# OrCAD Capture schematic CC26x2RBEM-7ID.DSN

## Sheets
1 Mechanical: size A4; title: CC26x2RBEM-7ID; rev: B0
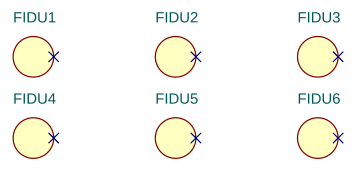
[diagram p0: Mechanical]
2 Revision
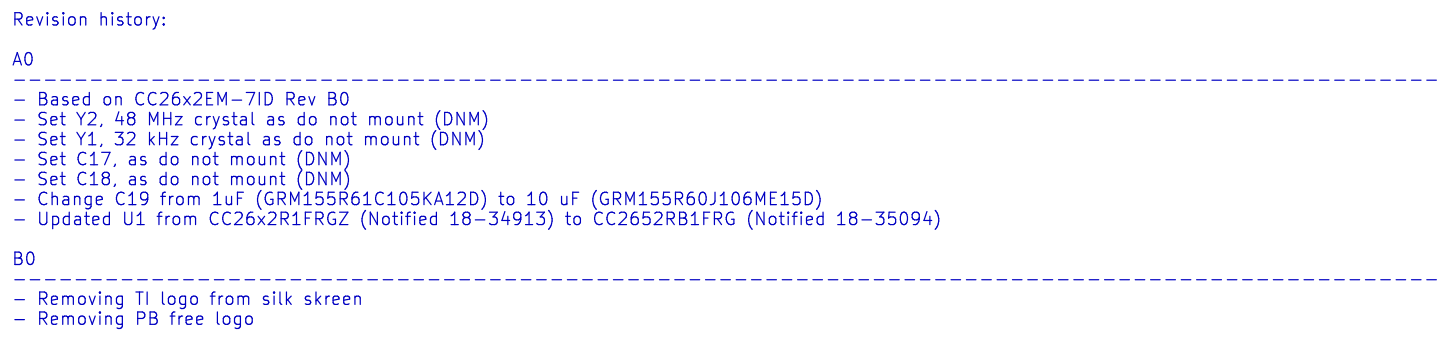
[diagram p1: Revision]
3 CC26x2RBEM-7ID: size A3
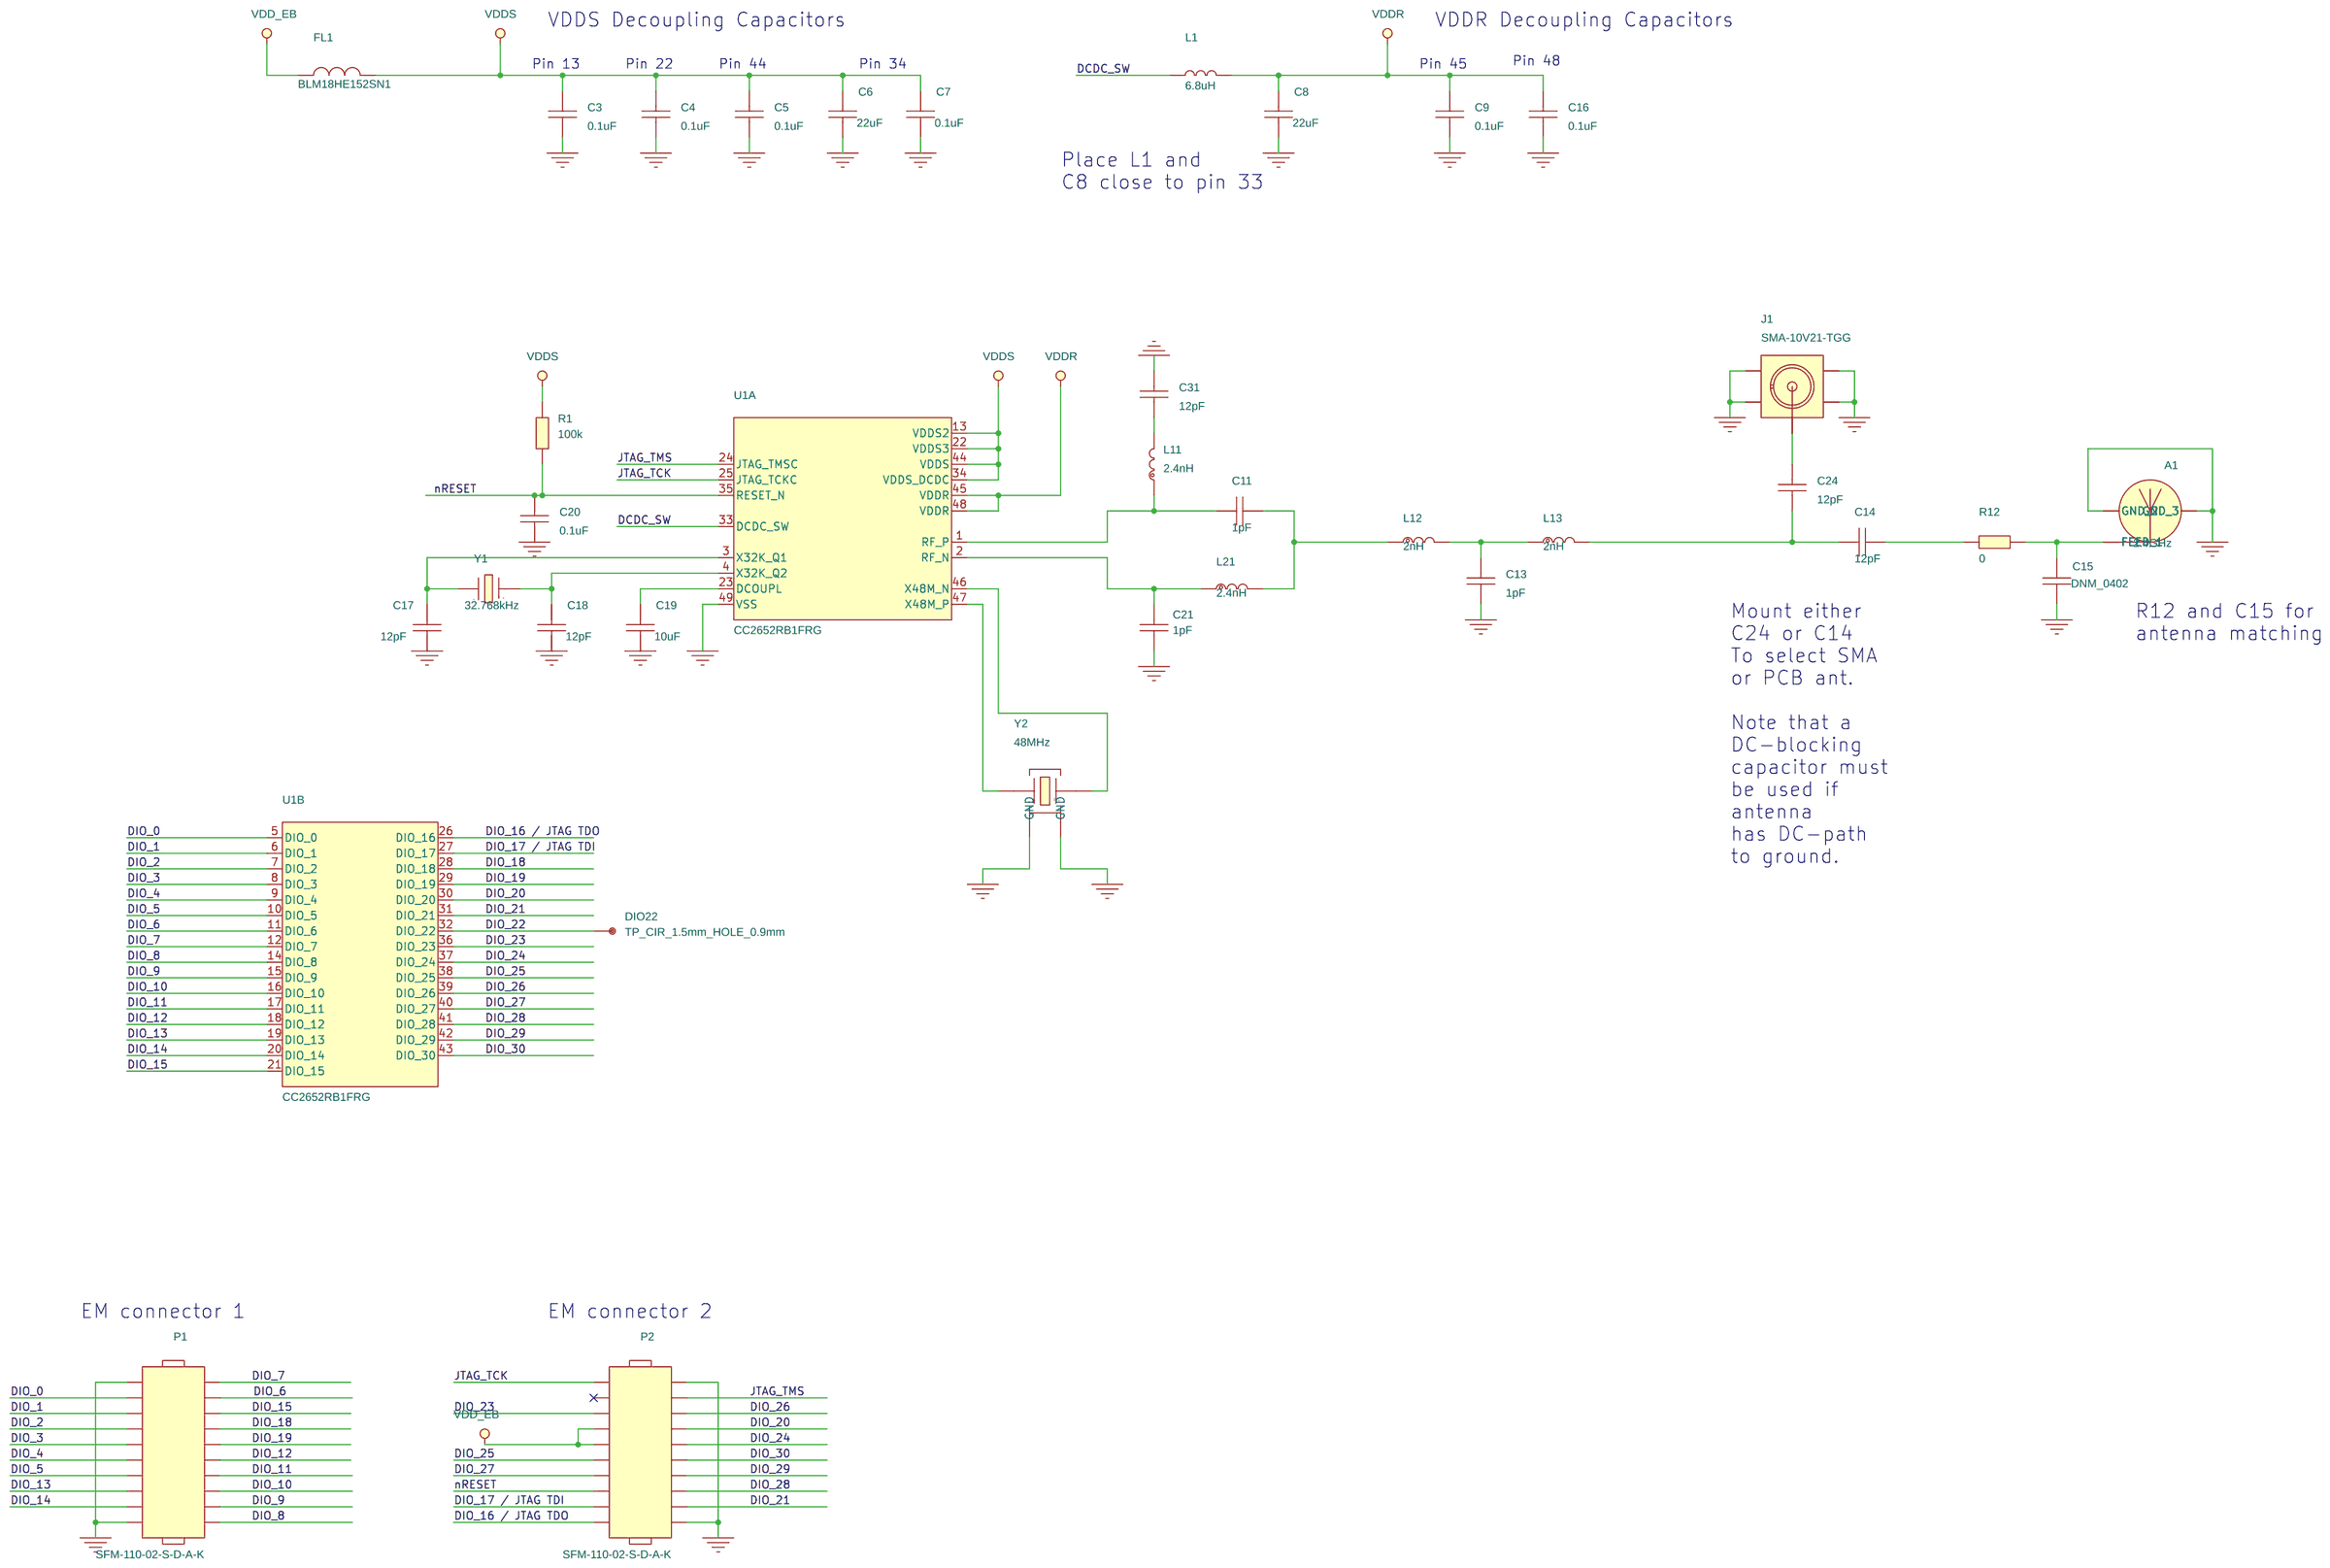
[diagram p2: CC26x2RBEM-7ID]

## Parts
sheet CC26x2RBEM-7ID
A1  2.4GHz  [ANTENNA_DN007AN]
C3  0.1uF  [CAPC1005X60B2N]
C4  0.1uF  [CAPC1005X60B2N]
C5  0.1uF  [CAPC1005X60B2N]
C6  22uF  [CAPC1608X100A2N]
C7  0.1uF  [CAPC1005X60B2N]
C8  22uF  [CAPC1608X100A2N]
C9  0.1uF  [CAPC1005X60B2N]
C11  1pF  [CAPC1005X60B2N]
C13  1pF  [CAPC1005X60B2N]
C14  12pF  [CAPC1005X60B2N]
C15  DNM_0402  [CAPC1005X60B2N]
C16  0.1uF  [CAPC1005X60B2N]
C17  12pF  [CAPC1005X60B2N]
C18  12pF  [CAPC1005X60B2N]
C19  10uF  [CAPC1005X65B2N]
C20  0.1uF  [CAPC1005X60B2N]
C21  1pF  [CAPC1005X60B2N]
C24  12pF  [CAPC1005X60B2N]
C31  12pF  [CAPC1005X60B2N]
DIO22  TP_CIR_1.5mm_HOLE_0.9mm  [TP150_90H]
FL1  BLM18HE152SN1  [FIL_BLM18HE152SN1DN]
J1  SMA-10V21-TGG  [HUSTSAN_SMA10V21TGGAN]
L1  6.8uH  [INDC2012X150A2N]
L11  2.4nH  [INDC1005X60D2N]
L12  2nH  [INDC1005X60D2N]
L13  2nH  [INDC1005X60D2N]
L21  2.4nH  [INDC1005X60D2N]
P1  SFM-110-02-S-D-A-K  [SAMTEC_SFM11002AN]
P2  SFM-110-02-S-D-A-K  [SAMTEC_SFM11002AN]
R1  100k  [RESC1005X40B2N]
R12  0  [RESC1005X40B2N]
U1  CC2652RB1FRG  [QFNFC50P700X700X100-49A2N]  (sections A,B)
Y1  32.768kHz  [XTAL_FC135_A2N]
Y2  48MHz  [OSCCC200X160X50-4B2N]
sheet Mechanical
FIDU1  FIDU_1MM  [FID100X115B]
FIDU2  FIDU_1MM  [FID100X115B]
FIDU3  FIDU_1MM  [FID100X115B]
FIDU4  FIDU_1MM  [FID100X115B]
FIDU5  FIDU_1MM  [FID100X115B]
FIDU6  FIDU_1MM  [FID100X115B]

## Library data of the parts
A1 = ANTENNA_DN007: ANTENNA, NON COMPONENT, 2.4GHz INVERTED F ANTENNA, NOT APPLY; Additional Datasheet URL: N/A; AutoDoc File: https://notefied-dynamic-precision.com/DB/Apps/Desktop/Item/Object.aspx?id=85542; BU Name: DYNAMIC PRECISION GDANSK; Budget Currency: N/A; Budget Price: N/A; CLASS: DISCRETE; Client Status: UNDER_REVIEW; Country of Origin: Missing Info; Datasheet URL: www.ti.com; Datasheet URL 1: http://www.ti.com/lit/an/swru120b/swru120b.pdf; Datasheet URL 2: N/A; Definied Quality: INDUSTRIAL; Esd Level: HBM 500V; Exclusive for Customers: TEXAS INSTRUMENTS NORWAY; FPLIST: ANTENNA_DN007N,ANTENNA_DN007AN,; MPN: DN007; MPN Status: ACTIVE; MSL: N/A; MTBF: N/A; MTBF Standard: N/A; Manufacturer: TEXAS INSTRUMENTS; Mass: N/A; Max Oper Temp: +85DEGC; Maximum Operating Temperature: +85DEGC; Min Oper Temp: -40DEGC; Minimum Operating Temperature: -40DEGC; Mounting Type: Not Apply; NOTE Status: PREFERRED; NOTEfied URL: https://notefied-dynamic-precision.com/NOTEfiedWebInterface/part/show?partNumber=13-00347; Notes: Custom Item; Old Footprint: ANTENNA_DN007N,ANTENNA_DN007AN; Packing Size: N/A; Packing Type: Missing Info; Part Number: 13-00347; Part Type: Mechanic|ANTENNA|NON COMPONENT; ROHS: Not Applicable; Revision: R019; RoHS Status: NOT_APPLICABLE; Status: Released; Texas Part Status: Under Review; Type: Mechanic; Vendor: TEXAS INSTRUMENTS; Vendor Part Number: DN007; Vendor Part Status: Active; WEIGHT: N/A
C3-C5 C9 C16 C20 = CAPACITOR: CAPACITOR, CERAMIC X7R, 0.1uF, 25V, -10%/+10%, -55DEGC/+125DEGC, 0402, SMD; Additional Datasheet URL: https://search.murata.co.jp/Ceramy/image/img/A01X/G101/ENG/GRM155R71E104KE14-01A.pdf; AutoDoc File: https://notefied-dynamic-precision.com/DB/Apps/Desktop/Item/Object.aspx?id=115293; BU Name: TEXAS INSTRUMENTS NORWAY; Client Status: UNDER_REVIEW; Datasheet URL: https://www.murata.com/~/media/webrenewal/support/library/catalog/products/capacitor/mlcc/c02e.ashx?la=en-gb; Datasheet URL 1: http://psearch.murata.com/capacitor/product/GRM155R71E104KE14%23.pdf; Datasheet URL 2: N/A; Dielectric Type: X7R; LifeCycle Status: ACTIVE; MPN: GRM155R70J104KA01D; MPN Status: ACTIVE; Manufacturer: MURATA; Mass: 0.0016g; Max Oper Temp: +125DEGC; Max Tol: +10%; Maximum Operating Temperature: +125DEGC; Maximum Tolerance: +10%; Min Oper Temp: -55DEGC; Min Tol: -10%; Minimum Operating Temperature: -55DEGC; Minimum Tolerance: -10%; Mounting Type: SMD; NOTE Status: PREFERRED; NOTEfied URL: https://notefied-dynamic-precision.com/NOTEfiedWebInterface/part/show?partNumber=02-07861; Old Footprint: CAPC1005X60N,0402; PCB Package: 0402; Packing Size: 10000; Packing Type: Tape & Reel; Part Number: 02-07861; Part Type: Capacitor|CERAMIC|0402|STANDARD; REACH/SVHC Compliance: Compliant; REACH/SVHC Details: SVHC List Version Jul 7, 2017; REACH/SVHC Source: REACH Declaration; REACH/SVHC Status: Unaffected; REACH/SVHC_COMPLIANCE: COMPLIANT; REACH/SVHC_DETAILS: SVHC LIST VERSION Jun 20, 2016; REACH/SVHC_SOURCE: REACH DECLARATION; REACH/SVHC_STATUS: UNAFFECTED; ROHS: Compliant; Rated Voltage: 25V; Revision: R014; RoHS Status: ROHS_COMPLIANT; Rtd Voltage: 25V; Status: Released; Texas Part Status: Under Review; Type: Capacitor; Vendor: MURATA; Vendor Part Number: GRM155R71E104KE14D; Vendor Part Status: NRND; WEIGHT: 0.0016g
C6 C8 = CAPACITOR: CAPACITOR, CERAMIC, X5R, 22uF, 6.3V, -20%/+20%, -55DEGC/+85DEGC, 0603, SMD; ALT_SYMBOLS: CAPC1608X100A2L,CAPC1608X100A2M; Additional Datasheet URL: https://search.murata.co.jp/Ceramy/image/img/A01X/G101/ENG/GRM188R60J226MEA0-01A.pdf; AutoDoc File: https://notefied-dynamic-precision.com/DB/Apps/Desktop/Item/Object.aspx?id=104385; BU Name: DYNAMIC PRECISION GDANSK; Budget Currency: EUR; Budget Price: 0.062; Budgetary Price: 0.062 EUR; Client Status: UNDER_REVIEW; Country of Origin: Japan; Datasheet URL: https://www.murata.com/~/media/webrenewal/support/library/catalog/products/capacitor/mlcc/c02e.ashx?la=en-gb; Datasheet URL 1: http://psearch.murata.com/capacitor/product/GRM188R60J226MEA0%23.pdf; Datasheet URL 2: N/A; Definied Quality: INDUSTRIAL; Dielectric Type: X5R; Esd Level: N/A; Lead Time: 26; MPN: GRM188R60J106ME47D; MPN Status: NRND; MSL: 1; MTBF: N/A; MTBF Standard: N/A; Manufacturer: MURATA; Mass: 0.0091g; Max Oper Temp: +85DEGC; Max Tol: +20%; Maximum Operating Temperature: +85DEGC; Maximum Tolerance: +20%; Min Oper Temp: -55DEGC; Min Tol: -20%; Minimum Operating Temperature: -55DEGC; Minimum Tolerance: -20%; Mounting Type: SMD; NOTE Status: PREFERRED; NOTEfied URL: https://notefied-dynamic-precision.com/NOTEfiedWebInterface/part/show?partNumber=02-07053; Old Footprint: CAPC1608X90N; PCB Package: 0603; Packing Size: 4000; Packing Type: Tape & Reel; Part Number: 02-07053; Part Type: Capacitor|CERAMIC|0603|STANDARD; REACH/SVHC Compliance: Compliant; REACH/SVHC Details: SVHC List Version Jul 7, 2017; REACH/SVHC Source: REACH Declaration; REACH/SVHC Status: Unaffected; REACH/SVHC_COMPLIANCE: COMPLIANT; REACH/SVHC_DETAILS: SVHC LIST VERSION Dec 17, 2015; REACH/SVHC_SOURCE: REACH DECLARATION; REACH/SVHC_STATUS: UNAFFECTED; ROHS: Compliant; Rated Voltage: 6.3V; Revision: R016; RoHS Status: ROHS_COMPLIANT; Rtd Voltage: 6.3V; Status: Released; Texas Part Status: Under Review; Type: Capacitor; Vendor: MURATA; Vendor Part Number: GRM188R60J226MEA0D; Vendor Part Status: Active; WEIGHT: 0.0091g
C7 = CAPACITOR: CAPACITOR, CERAMIC X7R, 0.1uF, 25V, -10%/+10%, -55DEGC/+125DEGC, 0402, SMD; Additional Datasheet URL: https://search.murata.co.jp/Ceramy/image/img/A01X/G101/ENG/GRM155R71E104KE14-01A.pdf; AutoDoc File: https://notefied-dynamic-precision.com/DB/Apps/Desktop/Item/Object.aspx?id=115293; BU Name: TEXAS INSTRUMENTS NORWAY; Cage Code: C0151; Client Status: UNDER_REVIEW; Datasheet URL: https://www.murata.com/~/media/webrenewal/support/library/catalog/products/capacitor/mlcc/c02e.ashx?la=en-gb; Datasheet URL 1: http://psearch.murata.com/capacitor/product/GRM155R71E104KE14%23.pdf; Datasheet URL 2: N/A; Dielectric Type: X7R; MPN: GRM188R71E104KA01D; MPN Status: ACTIVE; Manufacturer: MURATA; Mass: 0.0016g; Max Oper Temp: +125DEGC; Max Tol: +10%; Maximum Operating Temperature: +125DEGC; Maximum Tolerance: +10%; Min Oper Temp: -55DEGC; Min Tol: -10%; Minimum Operating Temperature: -55DEGC; Minimum Tolerance: -10%; Mounting Type: SMD; NOTE Status: PREFERRED; NOTEfied URL: https://notefied-dynamic-precision.com/NOTEfiedWebInterface/part/show?partNumber=02-07861; Old Footprint: CAPC1608X90N,0603; PCB Package: 0402; Packing Size: 10000; Packing Type: Tape & Reel; Part Number: 02-07861; Part Type: Capacitor|CERAMIC|0402|STANDARD; REACH/SVHC Compliance: Compliant; REACH/SVHC Details: SVHC List Version Jul 7, 2017; REACH/SVHC Source: REACH Declaration; REACH/SVHC Status: Unaffected; REACH/SVHC_COMPLIANCE: COMPLIANT; REACH/SVHC_DETAILS: SVHC LIST VERSION Jun 20, 2016; REACH/SVHC_SOURCE: REACH DECLARATION; REACH/SVHC_STATUS: UNAFFECTED; ROHS: Compliant; Rated Voltage: 25V; Revision: R014; RoHS Status: ROHS_COMPLIANT; Rtd Voltage: 25V; Status: Released; Texas Part Status: Under Review; Type: Capacitor; Vendor: MURATA; Vendor Part Number: GRM155R71E104KE14D; Vendor Part Status: NRND; WEIGHT: 0.0016g
C11 C13 C21 = CAPACITOR: CAPACITOR, CERAMIC C0G/NP0, 1pF, 50V, -0.25pF/ +0.25pF, -55DEGC/+125DEGC, 0402, SMD; Additional Datasheet URL: https://search.murata.co.jp/Ceramy/image/img/A01X/G101/ENG/GRM1555C1H1R0CA01-01A.pdf; AutoDoc File: https://notefied-dynamic-precision.com/DB/Apps/Desktop/Item/Object.aspx?id=113355; BU Name: TEXAS INSTRUMENTS NORWAY; Budget Currency: EUR; Budget Price: 0.006; Budgetary Price: 0.006 EUR; Country of Origin: Philippines; Datasheet URL: https://www.murata.com/~/media/webrenewal/support/library/catalog/products/capacitor/mlcc/c02e.ashx?la=en-gb; Datasheet URL 1: http://psearch.murata.com/capacitor/product/GRM1555C1H1R0CA01%23.pdf; Datasheet URL 2: http://search.murata.co.jp/Ceramy/image/img/w_hinm/L0005E.pdf; Dielectric Type: C0G/NP0; Exclusive for Customers: TEXAS INSTRUMENTS NORWAY; Lead Time: 12; MPN: GRM1555C1H1R0CA01D; MPN Status: ACTIVE; Manufacturer: MURATA; Mass: 0.0016g; Max Oper Temp: +125DEGC; Max Tol: +0.25pF; Maximum Operating Temperature: +125DEGC; Maximum Tolerance: +0.25pF; Min Oper Temp: -55DEGC; Min Tol: -0.25pF; Minimum Operating Temperature: -55DEGC; Minimum Tolerance: -0.25pF; Mounting Type: SMD; NOTE Status: PREFERRED; NOTEfied URL: https://notefied-dynamic-precision.com/NOTEfiedWebInterface/part/show?partNumber=02-07627; Notes: Standard item: Duplicate Reason: custom footprint for TEXAS INSTRUMENTS NORWAY.; Old Footprint: CAPC1005X60N; PCB Package: 0402; Packing Size: 10000; Packing Type: Tape & Reel; Part Number: 02-07627; Part Type: Capacitor|CERAMIC|0402|STANDARD; REACH/SVHC Compliance: Compliant; REACH/SVHC Details: SVHC List Version Jul 7, 2017; REACH/SVHC Source: REACH Declaration; REACH/SVHC Status: Unaffected; REACH/SVHC_COMPLIANCE: COMPLIANT; REACH/SVHC_DETAILS: SVHC LIST VERSION Dec 17, 2015; REACH/SVHC_SOURCE: REACH DECLARATION; REACH/SVHC_STATUS: UNAFFECTED; ROHS: Compliant; Rated Voltage: 50V; Revision: R016; RoHS Status: ROHS_COMPLIANT; Rtd Voltage: 50V; Status: Released; Texas Part Status: Under Review; Type: Capacitor; Vendor: MURATA; Vendor Part Number: GRM1555C1H1R0CA01D; Vendor Part Status: NRND; WEIGHT: 0.0016g
C14 C24 = CAPACITOR: CAPACITOR, CERAMIC C0G/NP0, 12pF, 50V, -5%/+5%, -55DEGC/+125DEGC, 0402, SMD; Additional Datasheet URL: https://search.murata.co.jp/Ceramy/image/img/A01X/G101/ENG/GRM1555C1H120JA01-01A.pdf; AutoDoc File: https://notefied-dynamic-precision.com/DB/Apps/Desktop/Item/Object.aspx?id=113345; BU Name: TEXAS INSTRUMENTS NORWAY; Budget Currency: EUR; Budget Price: 0.007; Budgetary Price: 0.007 EUR; Country of Origin: Philippines; Datasheet URL: https://www.murata.com/~/media/webrenewal/support/library/catalog/products/capacitor/mlcc/c02e.ashx?la=en-gb; Datasheet URL 1: http://psearch.murata.com/capacitor/product/GRM1555C1H120JA01%23.pdf; Datasheet URL 2: http://search.murata.co.jp/Ceramy/image/img/w_hinm/L0005E.pdf; Dielectric Type: C0G/NP0; Exclusive for Customers: TEXAS INSTRUMENTS NORWAY; Lead Time: 12; MPN: GRM1555C1H120JA01D; MPN Status: ACTIVE; Manufacturer: MURATA; Mass: 0.0016g; Max Oper Temp: +125DEGC; Max Tol: +5%; Maximum Operating Temperature: +125DEGC; Maximum Tolerance: +5%; Min Oper Temp: -55DEGC; Min Tol: -5%; Minimum Operating Temperature: -55DEGC; Minimum Tolerance: -5%; Mounting Type: SMD; NOTE Status: PREFERRED; NOTEfied URL: https://notefied-dynamic-precision.com/NOTEfiedWebInterface/part/show?partNumber=02-07617; Notes: Standard item: Duplicate Reason: custom footprint for TEXAS INSTRUMENTS NORWAY.; Old Footprint: CAPC1005X60N; PCB Package: 0402; Packing Size: 10000; Packing Type: Tape & Reel; Part Number: 02-07617; Part Type: Capacitor|CERAMIC|0402|STANDARD; REACH/SVHC Compliance: Compliant; REACH/SVHC Details: SVHC List Version Jul 7, 2017; REACH/SVHC Source: REACH Declaration; REACH/SVHC Status: Unaffected; REACH/SVHC_COMPLIANCE: COMPLIANT; REACH/SVHC_DETAILS: SVHC LIST VERSION Dec 17, 2015; REACH/SVHC_SOURCE: REACH DECLARATION; REACH/SVHC_STATUS: UNAFFECTED; ROHS: Compliant; Rated Voltage: 50V; Revision: R016; RoHS Status: ROHS_COMPLIANT; Rtd Voltage: 50V; Status: Released; Texas Part Status: Under Review; Type: Capacitor; Vendor: MURATA; Vendor Part Number: GRM1555C1H120JA01D; Vendor Part Status: NRND; WEIGHT: 0.0016g
C15 = CAPACITOR: CAPACITOR, CERAMIC, TBD, 0402, SMD, DNM; Additional Datasheet URL: N/A; AutoDoc File: https://notefied-dynamic-precision.com/DB/Apps/Desktop/Item/Object.aspx?id=113344; BU Name: TEXAS INSTRUMENTS NORWAY; Country of Origin: Missing Info; Datasheet URL: N/A; Datasheet URL 1: N/A; Datasheet URL 2: N/A; Dielectric Type: MISSING-INFO; Exclusive for Customers: TEXAS INSTRUMENTS NORWAY; MPN: CAPACITOR_0402_DNM_N/A_M; MPN Status: ACTIVE; Manufacturer: Manufacturer selection; Mass: N/A; Max Oper Temp: +125DEGC; Maximum Operating Temperature: +125DEGC; Min Oper Temp: -55DEGC; Minimum Operating Temperature: -55DEGC; Mounting Type: SMD; NOTE Status: PREFERRED; NOTEfied URL: https://notefied-dynamic-precision.com/NOTEfiedWebInterface/part/show?partNumber=02-07616; Notes: Standard item: Duplicate Reason: custom footprint for TEXAS INSTRUMENTS NORWAY.; Old Footprint: CAPC1005X60N; PCB Package: 0402; Part Number: 02-07616; Part Type: Capacitor|CERAMIC|0402|STANDARD; ROHS: Compliant; Revision: R014; RoHS Status: ROHS_COMPLIANT; Status: Released; Texas Part Status: Under Review; Type: Capacitor; Vendor: MANUFACTURER SELECTION; Vendor Part Number: CAPACITOR_TBD_0402_DNM; Vendor Part Status: Active; Weight: N/A
C17 C18 = CAPACITOR: CAPACITOR, CERAMIC C0G/NP0, 12pF, 50V, -5%/+5%, -55DEGC/+125DEGC, 0402, SMD; Additional Datasheet URL: https://search.murata.co.jp/Ceramy/image/img/A01X/G101/ENG/GRM1555C1H120JA01-01A.pdf; AutoDoc File: https://notefied-dynamic-precision.com/DB/Apps/Desktop/Item/Object.aspx?id=113345; BU Name: TEXAS INSTRUMENTS NORWAY; Budget Currency: EUR; Budget Price: 0.007; Budgetary Price: 0.007 EUR; Country of Origin: Philippines; Datasheet URL: https://www.murata.com/~/media/webrenewal/support/library/catalog/products/capacitor/mlcc/c02e.ashx?la=en-gb; Datasheet URL 1: http://psearch.murata.com/capacitor/product/GRM1555C1H120JA01%23.pdf; Datasheet URL 2: http://search.murata.co.jp/Ceramy/image/img/w_hinm/L0005E.pdf; Definied Quality: INDUSTRIAL; Dielectric Type: C0G/NP0; Esd Level: N/A; Exclusive for Customers: TEXAS INSTRUMENTS NORWAY; Lead Time: 12; LifeCycle Status: ACTIVE; MPN: CAPACITOR_0402_12pF_C0G/NP0_M_+/-5%_50V; MPN Status: ACTIVE; MSL: N/A; MTBF: N/A; MTBF Standard: N/A; Manufacturer: MANUFACTURER SELECTION; Mass: 0.0016g; Max Oper Temp: +125DEGC; Max Tol: +5%; Maximum Operating Temperature: +125DEGC; Maximum Tolerance: +5%; Min Oper Temp: -55DEGC; Min Tol: -5%; Minimum Operating Temperature: -55DEGC; Minimum Tolerance: -5%; Mounting Type: SMD; NOTE Status: PREFERRED; NOTEfied URL: https://notefied-dynamic-precision.com/NOTEfiedWebInterface/part/show?partNumber=02-07617; Notes: Standard item: Duplicate Reason: custom footprint for TEXAS INSTRUMENTS NORWAY.; Old Footprint: CAPC1005X60N; PCB Package: 0402; Packing Size: 10000; Packing Type: Tape & Reel; Part Number: 02-07617; Part Type: Capacitor|CERAMIC|0402|STANDARD; REACH/SVHC Compliance: Compliant; REACH/SVHC Details: SVHC List Version Jul 7, 2017; REACH/SVHC Source: REACH Declaration; REACH/SVHC Status: Unaffected; REACH/SVHC_COMPLIANCE: COMPLIANT; REACH/SVHC_DETAILS: SVHC LIST VERSION Dec 17, 2015; REACH/SVHC_SOURCE: REACH DECLARATION; REACH/SVHC_STATUS: UNAFFECTED; ROHS: Compliant; Rated Voltage: 50V; Revision: R016; RoHS Status: ROHS_COMPLIANT; Rtd Voltage: 50V; Status: Released; Texas Part Status: Under Review; Type: Capacitor; Vendor: MURATA; Vendor Part Number: GRM1555C1H120JA01D; Vendor Part Status: NRND; WEIGHT: 0.0016g
C19 = CAPACITOR: CAPACITOR, CERAMIC X5R, 10uF, 6.3V, -20%/+20%, -55DEGC/+85DEGC, 0402, SMD; Additional Datasheet URL: https://psearch.en.murata.com/capacitor/product/GRM155R60J106ME15%23.pdf?graph=1052f0115a5050a7826442b7332e4634; AutoDoc File: https://notefied-dynamic-precision.com/DB/Apps/Desktop/Item/Object.aspx?id=115295; BU Name: TEXAS INSTRUMENTS NORWAY; Client Status: UNDER_REVIEW; Datasheet URL: https://search.murata.co.jp/Ceramy/image/img/A01X/G101/ENG/GRM155R60J106ME15-01A.pdf; Datasheet URL 1: http://psearch.murata.com/capacitor/product/GRM155R61C105KA12%23.pdf; Datasheet URL 2: N/A; Definied Quality: INDUSTRIAL; Dielectric Type: X5R; Esd Level: N/A; MPN: GRM155R61A105KE15D; MPN Status: ACTIVE; MSL: 1; MTBF: N/A; MTBF Standard: N/A; Manufacturer: MURATA; Mass: 0.0025g; Max Oper Temp: +85DEGC; Max Tol: +10%; Maximum Operating Temperature: +85DEGC; Maximum Tolerance: +20%; Min Oper Temp: -55DEGC; Min Tol: -10%; Minimum Operating Temperature: -55DEGC; Minimum Tolerance: -20%; Mounting Type: SMD; NOTE Status: PREFERRED; NOTEfied URL: https://notefied-dynamic-precision.com/NOTEfiedWebInterface/part/show?partNumber=02-09408; Old Footprint: CAPC1005X60N,0402; PCB Package: 0402; Packing Size: 10000; Packing Type: Tape & Reel; Part Number: 02-09408; Part Type: Capacitor|CERAMIC|0402|STANDARD; REACH/SVHC Compliance: Compliant; REACH/SVHC Details: SVHC List Version Jul 16, 2019; REACH/SVHC Source: REACH Declaration; REACH/SVHC Status: Unaffected; REACH/SVHC_COMPLIANCE: COMPLIANT; REACH/SVHC_DETAILS: SVHC LIST VERSION Jun 20, 2016; REACH/SVHC_SOURCE: REACH DECLARATION; REACH/SVHC_STATUS: UNAFFECTED; ROHS: Compliant; Rated Voltage: 6.3V; Revision: R001; RoHS Status: ROHS_COMPLIANT; Rtd Voltage: 16V; Status: Released; Texas Part Status: Under Review; Type: Capacitor; Vendor: MURATA; Vendor Part Number: GRM155R60J106ME15D; Vendor Part Status: Active; WEIGHT: 0.0016g
C31 = CAPACITOR: CAPACITOR, CERAMIC C0G/NP0, 12pF, 50V, -5%/+5%, -55DEGC/+125DEGC, 0402, SMD; Additional Datasheet URL: https://search.murata.co.jp/Ceramy/image/img/A01X/G101/ENG/GRM1555C1H120JA01-01A.pdf; AutoDoc File: https://notefied-dynamic-precision.com/DB/Apps/Desktop/Item/Object.aspx?id=113345; BU Name: TEXAS INSTRUMENTS NORWAY; Budget Currency: EUR; Budget Price: 0.007; Budgetary Price: 0.007 EUR; Country of Origin: Philippines; Datasheet URL: https://www.murata.com/~/media/webrenewal/support/library/catalog/products/capacitor/mlcc/c02e.ashx?la=en-gb; Datasheet URL 1: http://psearch.murata.com/capacitor/product/GRM1555C1H120JA01%23.pdf; Datasheet URL 2: http://search.murata.co.jp/Ceramy/image/img/w_hinm/L0005E.pdf; Dielectric Type: C0G/NP0; Exclusive for Customers: TEXAS INSTRUMENTS NORWAY; Lead Time: 12; MPN: GRM1555C1H6R8CA01D; MPN Status: ACTIVE; Manufacturer: MURATA; Mass: 0.0016g; Max Oper Temp: +125DEGC; Max Tol: +5%; Maximum Operating Temperature: +125DEGC; Maximum Tolerance: +5%; Min Oper Temp: -55DEGC; Min Tol: -5%; Minimum Operating Temperature: -55DEGC; Minimum Tolerance: -5%; Mounting Type: SMD; NOTE Status: PREFERRED; NOTEfied URL: https://notefied-dynamic-precision.com/NOTEfiedWebInterface/part/show?partNumber=02-07617; Notes: Standard item: Duplicate Reason: custom footprint for TEXAS INSTRUMENTS NORWAY.; Old Footprint: CAPC1005X60N; PCB Package: 0402; Packing Size: 10000; Packing Type: Tape & Reel; Part Number: 02-07617; Part Type: Capacitor|CERAMIC|0402|STANDARD; REACH/SVHC Compliance: Compliant; REACH/SVHC Details: SVHC List Version Jul 7, 2017; REACH/SVHC Source: REACH Declaration; REACH/SVHC Status: Unaffected; REACH/SVHC_COMPLIANCE: COMPLIANT; REACH/SVHC_DETAILS: SVHC LIST VERSION Dec 17, 2015; REACH/SVHC_SOURCE: REACH DECLARATION; REACH/SVHC_STATUS: UNAFFECTED; ROHS: Compliant; Rated Voltage: 50V; Revision: R016; RoHS Status: ROHS_COMPLIANT; Rtd Voltage: 50V; Status: Released; Texas Part Status: Under Review; Type: Capacitor; Vendor: MURATA; Vendor Part Number: GRM1555C1H120JA01D; Vendor Part Status: NRND; WEIGHT: 0.0016g
DIO22 = TEST_POINT: NON COMPONENT, TEST POINT, CIRCULAR 1.5mm, HOLE 0.9mm, PTH; Additional Datasheet URL: N/A; AutoDoc File: https://notefied-dynamic-precision.com/DB/Apps/Desktop/Item/Object.aspx?id=84966; BU Name: DYNAMIC PRECISION GDANSK; CLASS: IO; Country of Origin: Missing Info; Datasheet URL: N/A; FPLIST: TP150_90H,; Mass: N/A; Mounting Type: PTH; NOTEfied URL: https://notefied-dynamic-precision.com/NOTEfiedWebInterface/part/show?partNumber=19-00299; Packing Size: N/A; Packing Type: Missing Info; Part Number: 19-00299; Part Type: Non Component|TEST POINT; ROHS: Not Applicable; Revision: R018; Status: Released; Texas Part Status: Under Review; Type: Non Component; Vendor: NON_COMPONENT; Vendor Part Status: Active
FL1 = FILTER_2PIN: FILTER, EMI, FERRITE BEAD, 1500@100MHz, -25%/+25%, -55DEGC/+125DEGC, 0603, SMD; ALT_SYMBOLS: FIL_BLM18HE152SN1DL,FIL_BLM18HE152SN1DM; Additional Datasheet URL: https://www.murata.com/en-eu/products/productdata/8796741599262/ENFA0004.pdf?1441769419000; AutoDoc File: https://notefied-dynamic-precision.com/DB/Apps/Desktop/Item/Object.aspx?id=85575; BU Name: DYNAMIC PRECISION GDANSK; Budget Currency: EUR; Budget Price: 0.065; Budgetary Price: 0.065 EUR; CLASS: IC; Client Status: UNDER_REVIEW; Country of Origin: Japan,Singapore,Thailand; Datasheet URL: https://www.murata.com/~/media/webrenewal/support/library/catalog/products/emc/emifil/c31e.ashx; Datasheet URL 1: http://search.murata.co.jp/Ceramy/image/img/PDF/ENG/L0110S0101BLM18H.pdf; Datasheet URL 2: http://search.murata.co.jp/Ceramy/image/img/w_hinm/L0110E.pdf; Frequency: 100MHz; Impedance: 1500; Inductance: N/A; Lead Time: 9; MPN: BLM18HE152SN1D; MPN Status: ACTIVE; Manufacturer: MURATA; Mass: 0.006g; Max Oper Temp: +125DEGC; Max Tol: +25%; Maximum Operating Temperature: +125DEGC; Maximum Tolerance: +25%; Min Oper Temp: -55DEGC; Min Tol: -25%; Minimum Operating Temperature: -55DEGC; Minimum Tolerance: -25%; Mounting Type: SMD; NOTE Status: PREFERRED; NOTEfied URL: https://notefied-dynamic-precision.com/NOTEfiedWebInterface/part/show?partNumber=04-00470; PCB Package: 0603; Packing Size: 4000; Packing Type: Tape & Reel; Part Number: 04-00470; Part Type: Filter|EMI|FERRITE BEAD|0603; REACH/SVHC Compliance: Compliant; REACH/SVHC Details: SVHC List Version Jul 7, 2017; REACH/SVHC Source: REACH Declaration; REACH/SVHC Status: Unaffected; REACH/SVHC_COMPLIANCE: COMPLIANT; REACH/SVHC_DETAILS: SVHC LIST VERSION Dec 17, 2015; REACH/SVHC_SOURCE: REACH DECLARATION; REACH/SVHC_STATUS: UNAFFECTED; ROHS: Compliant; Rated Current: 0.5A; Rated Voltage: N/A; Revision: R015; RoHS Status: ROHS_COMPLIANT; Rtd Current: 0.5A; Rtd Voltage: N/A; Status: Released; Texas Part Status: Under Review; Type: Filter; Vendor: MURATA; Vendor Part Number: BLM18HE152SN1D; Vendor Part Status: Active; WEIGHT: 0.006g
J1 = CONN_COAX_1+4: CONNECTOR, COAX, RF, FEMALE, STRAIGHT, 1 PIN, SMD; ALT_SYMBOLS: HUSTSAN_SMA10V21TGGL,HUSTSAN_SMA10V21TGGM; Additional Datasheet URL: http://www.hustsan.com.tw/cgi-bin/productfn/pdt_detail_lst.pl?ProdID=143; AutoDoc File: https://notefied-dynamic-precision.com/DB/Apps/Desktop/Item/Object.aspx?id=84956; BU Name: DYNAMIC PRECISION GDANSK; Budget Currency: N/A; Budget Price: N/A; CLASS: IO; Client Status: UNDER_REVIEW; Country of Origin: Taiwan; Datasheet URL: http://www.hustsan.com.tw/uploaddir/product/SMA-10V21.pdf; Datasheet URL 1: http://www.hustsan.com.tw/uploaddir/product/SMA-10V21.pdf; Datasheet URL 2: http://www.hustsan.com.tw/cgi-bin/productfn/pdt_detail_lst.pl?ProdID=143; FPLIST: HUSTSAN_SMA10V21TGGAN,HUSTSAN_SMA10V21TGGN; MPN Status: ACTIVE; MSL: N/A; Manufacturer: HUS-TSAN; Mass: N/A; Mounting Type: SMD; NOTE Status: PREFERRED; NOTEfied URL: https://notefied-dynamic-precision.com/NOTEfiedWebInterface/part/show?partNumber=06-02188; No Of Pos: 1; Number of Positions: 1; Old Footprint: HUSTSAN_SMA10V21TGGAN,HUSTSAN_SMA10V21TGGN; Packing Size: 350; Packing Type: Tape & Reel; Part Number: 06-02188; Part Type: Connector|COAX|RF; REACH/SVHC Compliance: Compliant; REACH/SVHC Details: SVHC List Version Jun 20, 2016; REACH/SVHC Source: REACH Declaration; REACH/SVHC Status: Unaffected; ROHS: Compliant; Revision: R014; RoHS Status: ROHS_COMPLIANT; Status: Released; Texas Part Status: Under Review; Type: Connector; Vendor: HUS-TSAN; Vendor Part Status: Active; WEIGHT: N/A
L1 = INDUCTOR: INDUCTOR, STANDARD, FERRITE CORE, 6.8uH, -20%/+20%, 0.11A, -55DEGC/+125DEGC, 0805, SMD; ALT_SYMBOLS: INDC2012X150A2L,INDC2012X150A2M; Additional Datasheet URL: https://product.tdk.com/en/search/inductor/inductor/smd/info?part_no=MLZ2012N6R8LT000; AutoDoc File: https://notefied-dynamic-precision.com/DB/Apps/Desktop/Item/Object.aspx?id=102853; BU Name: DYNAMIC PRECISION GDANSK; Budget Currency: EUR; Budget Price: 0.059; Budgetary Price: 0.045 USD; CLASS: DISCRETE; Client Status: UNDER_REVIEW; Core Material: FERRITE; Country of Origin: Missing Info; Datasheet URL: http://product.tdk.com/info/en/catalog/datasheets/inductor_commercial_decoupling_mlz2012_en.pdf; Datasheet URL 1: https://product.tdk.com/en/search/inductor/inductor/smd/info?part_no=MLZ2012N6R8LT000; Datasheet URL 2: http://product.tdk.com/info/en/catalog/datasheets/inductor_commercial_decoupling_mlz2012_en.pdf; Lead Time: 10; MPN: CKS2125100M-T; MPN Status: ACTIVE; Manufacturer: TAIYO YUDEN; Mass: 0.01g; Max Oper Temp: +125DEGC; Max Tol: +20%; Maximum Operating Temperature: +125DEGC; Maximum Tolerance: +20%; Min Oper Temp: -55DEGC; Min Tol: -20%; Minimum Operating Temperature: -55DEGC; Minimum Tolerance: -20%; Mounting Type: SMD; NOTE Status: PREFERRED; NOTEfied URL: https://notefied-dynamic-precision.com/NOTEfiedWebInterface/part/show?partNumber=03-07266; Old Footprint: INDC2012X150N; PCB Package: 0805; Packing Size: 4000; Packing Type: Tape & Reel; Part Number: 03-07266; Part Type: Inductor|STANDARD|CHIP|0805; REACH/SVHC Compliance: Compliant; REACH/SVHC Details: SVHC List Version Jan 12, 2017; REACH/SVHC Source: REACH Declaration; REACH/SVHC Status: Unaffected; REACH/SVHC_COMPLIANCE: COMPLIANT; REACH/SVHC_DETAILS: SVHC LIST VERSION Dec 17, 2015; REACH/SVHC_SOURCE: REACH DECLARATION; REACH/SVHC_STATUS: UNAFFECTED; ROHS: Compliant; Resistance: 0.25; Revision: R014; RoHS Status: ROHS_COMPLIANT; Rtd Current: 1.1A; Status: Released; Texas Part Status: Under Review; Type: Inductor; Vendor: TDK; Vendor Part Number: MLZ2012N6R8LT000; Vendor Part Status: Active; Weight: 0.01g
L11 L21 = INDUCTOR_HOR_1_2: INDUCTOR, RF, CHIP, NON-MAGNETIC CORE, 2.4nH, -0.3nH/+0.3nH, 0.3A, -55DEGC/+125DEGC, 0402, SMD; Additional Datasheet URL: https://search.murata.co.jp/Ceramy/image/img/P02/JELF243B-0010.pdf; AutoDoc File: https://notefied-dynamic-precision.com/DB/Apps/Desktop/Item/Object.aspx?id=113363; BU Name: TEXAS INSTRUMENTS NORWAY; Budget Currency: EUR; Budget Price: 0.031; Budgetary Price: 0.031 EUR; Client Status: UNDER_REVIEW; Core Material: NON-MAGNETIC; Country of Origin: Japan,Singapore; Datasheet URL: https://www.murata.com/~/media/webrenewal/support/library/catalog/products/inductor/chip/o05e.ashx?la=en-gb; Datasheet URL 1: http://psearch.murata.com/inductor/product/LQG15HS2N4S02%23.pdf; Datasheet URL 2: http://www.murata.com/~/media/webrenewal/support/library/catalog/products/inductor/chip/o05e.ashx; Exclusive for Customers: TEXAS INSTRUMENTS NORWAY; Frequency: 6GHz; Lead Time: 9; Mass: 0.001g; Max Oper Temp: +125DEGC; Max Tol: +0.3nH; Maximum Operating Temperature: +125DEGC; Maximum Tolerance: +0.3nH; Min Oper Temp: -55DEGC; Min Tol: -0.3nH; Minimum Operating Temperature: -55DEGC; Minimum Tolerance: -0.3nH; Mounting Type: SMD; NOTEfied URL: https://notefied-dynamic-precision.com/NOTEfiedWebInterface/part/show?partNumber=03-07526; Notes: Standard item: Duplicate Reason: custom footprint for TEXAS INSTRUMENTS NORWAY.; PCB Package: 0402; Packing Size: 10000; Packing Type: Tape & Reel; Part Number: 03-07526; Part Type: Inductor|RF|CHIP|0402; REACH/SVHC Compliance: Compliant; REACH/SVHC Details: SVHC List Version Jul 7, 2017; REACH/SVHC Source: REACH Declaration; REACH/SVHC Status: Unaffected; REACH/SVHC_COMPLIANCE: COMPLIANT; REACH/SVHC_DETAILS: SVHC LIST VERSION Dec 17, 2015; REACH/SVHC_SOURCE: REACH DECLARATION; REACH/SVHC_STATUS: UNAFFECTED; ROHS: Compliant; Revision: R019; RoHS Status: ROHS_COMPLIANT; Rtd Current: 0.3A; Status: Released; Texas Part Status: Under Review; Type: Inductor; Vendor: MURATA; Vendor Part Number: LQG15HS2N4S02D; Vendor Part Status: Active; Weight: 0.001g
L12 L13 = INDUCTOR_HOR_1_2: INDUCTOR, RF, CHIP, NON-MAGNETIC CORE, 2nH, -0.3nH/+0.3nH, 0.3A, -55DEGC/+125DEGC, 0402, SMD; Additional Datasheet URL: https://search.murata.co.jp/Ceramy/image/img/P02/JELF243B-0010.pdf; AutoDoc File: https://notefied-dynamic-precision.com/DB/Apps/Desktop/Item/Object.aspx?id=113364; BU Name: TEXAS INSTRUMENTS NORWAY; Budget Currency: EUR; Budget Price: 0.031; Budgetary Price: 0.031 EUR; Client Status: UNDER_REVIEW; Core Material: NON-MAGNETIC; Country of Origin: Japan,Singapore; Datasheet URL: https://www.murata.com/~/media/webrenewal/support/library/catalog/products/inductor/chip/o05e.ashx?la=en-gb; Datasheet URL 1: http://psearch.murata.com/inductor/product/LQG15HS2N0S02%23.pdf; Datasheet URL 2: http://www.murata.com/~/media/webrenewal/support/library/catalog/products/inductor/chip/o05e.ashx; Exclusive for Customers: TEXAS INSTRUMENTS NORWAY; Frequency: 6GHz; Lead Time: 10; Mass: 0.001g; Max Oper Temp: +125DEGC; Max Tol: +0.3nH; Maximum Operating Temperature: +125DEGC; Maximum Tolerance: +0.3nH; Min Oper Temp: -55DEGC; Min Tol: -0.3nH; Minimum Operating Temperature: -55DEGC; Minimum Tolerance: -0.3nH; Mounting Type: SMD; NOTEfied URL: https://notefied-dynamic-precision.com/NOTEfiedWebInterface/part/show?partNumber=03-07527; Notes: Standard item: Duplicate Reason: custom footprint for TEXAS INSTRUMENTS NORWAY.; PCB Package: 0402; Packing Size: 10000; Packing Type: Tape & Reel; Part Number: 03-07527; Part Type: Inductor|RF|CHIP|0402; REACH/SVHC Compliance: Compliant; REACH/SVHC Details: SVHC List Version Jul 7, 2017; REACH/SVHC Source: REACH Declaration; REACH/SVHC Status: Unaffected; REACH/SVHC_COMPLIANCE: COMPLIANT; REACH/SVHC_DETAILS: SVHC LIST VERSION Dec 17, 2015; REACH/SVHC_SOURCE: REACH DECLARATION; REACH/SVHC_STATUS: UNAFFECTED; ROHS: Compliant; Revision: R018; RoHS Status: ROHS_COMPLIANT; Rtd Current: 0.3A; Status: Released; Texas Part Status: Under Review; Type: Inductor; Vendor: MURATA; Vendor Part Number: LQG15HS2N0S02D; Vendor Part Status: Active; Weight: 0.001g
P1 P2 = CONN_HEADER_2X10_P_S: CONNECTOR, HEADER, FEMALE, STRAIGHT, 2 ROWS, 20 PINS, PITCH 1.27mm, SMD; ALT_SYMBOLS: SAMTEC_SFM11002AL,SAMTEC_SFM11002AM; Additional Datasheet URL: http://suddendocs.samtec.com/prints/sfm-1xx-xx-xxx-d-xxx-mkt.pdf; Alt IPC Footprints: SAMTEC_SFM11002AL,SAMTEC_SFM11002AM; AutoDoc File: https://notefied-dynamic-precision.com/DB/Apps/Desktop/Item/Object.aspx?id=85603; BU Name: TEXAS INSTRUMENTS NORWAY; Budget Currency: USD; Budget Price: 3.180; Budgetary Price: 5.3504 USD; CLASS: IO; Client Status: UNDER_REVIEW; Country of Origin: China,Costa Rica,Malaysia,Singapore,United States; Datasheet URL: http://suddendocs.samtec.com/catalog_english/sfm.pdf; Datasheet URL 1: http://suddendocs.samtec.com/catalog_english/sfm.pdf; Datasheet URL 2: http://suddendocs.samtec.com/prints/sfm-1xx-xx-xxx-d-xxx-mkt.pdf; Lead Time: 4; MPN: SFM-110-02-SM-D-A-K-TR; MPN Status: ACTIVE; Manufacturer: SAMTEC; Mass: 0.30875g; Max Oper Temp: +125DEGC; Maximum Operating Temperature: +125DEGC; Min Oper Temp: -55DEGC; Minimum Operating Temperature: -55DEGC; Mounting Type: SMD; NOTE Status: PREFERRED; NOTEfied URL: https://notefied-dynamic-precision.com/NOTEfiedWebInterface/part/show?partNumber=06-02251; No Of Pos: 20; No Of Rows: 2; Number of Positions: 20; Number of Rows: 2; Packing Size: 725; Packing Type: Tape & Reel; Part Number: 06-02251; Part Type: Connector|HEADER|STANDARD; Pitch: 1.27mm; REACH/SVHC Compliance: Compliant; REACH/SVHC Details: SVHC List Version Jan 12, 2017; REACH/SVHC Source: Material Declaration; REACH/SVHC Status: Unaffected; ROHS: Compliant; Revision: R013; RoHS Status: ROHS_COMPLIANT; Status: Released; Texas Part Status: Under Review; Type: Connector; Vendor: SAMTEC; Vendor Part Number: SFM-110-02-SM-D-A-K-TR; Vendor Part Status: Active; Weight: 0.30875g
R1 = RESISTOR: RESISTOR, THICK FILM, 100k, -5%/+5%, 0.063W, 50V, -55DEGC/+155DEGC, 0402, SMD; Additional Datasheet URL: N/A; AutoDoc File: https://notefied-dynamic-precision.com/DB/Apps/Desktop/Item/Object.aspx?id=114565; BU Name: TEXAS INSTRUMENTS NORWAY; Budget Currency: EUR; Budget Price: 0.014; Budgetary Price: 0.014 EUR; CLASS: DISCRETE; Client Status: UNDER_REVIEW; Country of Origin: United States; Datasheet URL: https://www.vishay.com/docs/20035/dcrcwe3.pdf; Datasheet URL 1: http://www.vishay.com/docs/20035/dcrcwe3.pdf; Datasheet URL 2: N/A; Definied Quality: INDUSTRIAL; Esd Level: N/A; Exclusive for Customers: TEXAS INSTRUMENTS NORWAY; Lead Time: 18; LifeCycle Status: ACTIVE; MPN: RESISTOR_0402_100k_+/-1%_50V_0.063W_M_+/-100PPM; MPN Status: ACTIVE; MSL: N/A; MTBF: N/A; MTBF Standard: N/A; Manufacturer: MANUFACTURER SELECTION; Mass: 0.00065g; Max Oper Temp: +155DEGC; Max TC: +200PPM/DEGC; Max Tol: +5%; Maximum Operating Temperature: +155DEGC; Maximum Temperature Coefficient: +200PPM/DEGC; Maximum Tolerance: +5%; Min Oper Temp: -55DEGC; Min TC: -200PPM/DEGC; Min Tol: -5%; Minimum Operating Temperature: -55DEGC; Minimum Temperature Coeficient: -200PPM/DEGC; Minimum Tolerance: -5%; Mounting Type: SMD; NOTE Status: PREFERRED; NOTEfied URL: https://notefied-dynamic-precision.com/NOTEfiedWebInterface/part/show?partNumber=01-22492; Notes: Standard item: Duplicate Reason: custom footprint for TEXAS INSTRUMENTS NORWAY.; Old Footprint: RESC1005X40N; PCB Package: 0402; Packing Size: 10000; Packing Type: Tape & Reel; Part Number: 01-22492; Part Type: Resistor|0402|STANDARD; REACH/SVHC Compliance: Compliant; REACH/SVHC Details: SVHC List Version Jun 20, 2016; REACH/SVHC Source: Material Declaration; REACH/SVHC Status: Unaffected; REACH/SVHC_COMPLIANCE: COMPLIANT; REACH/SVHC_DETAILS: SVHC LIST VERSION Jun 20, 2016; REACH/SVHC_SOURCE: MATERIAL DECLARATION; REACH/SVHC_STATUS: UNAFFECTED; ROHS: Exempt; Rated Current: N/A; Rated Power: 0.063W; Rated Voltage: 50V; Resistor Type: THICK FILM; Revision: R014; RoHS Status: ROHS_COMPLIANT; Rtd Current: N/A; Rtd Power: 0.063W; Rtd Voltage: 50V; Status: Released; Texas Part Status: Under Review; Type: Resistor; Vendor: VISHAY; Vendor Part Number: CRCW0402100KJNED; Vendor Part Status: Active; WEIGHT: 0.00065g
R12 = RESISTOR: RESISTOR, THICK FILM, 0, 0R/+0.02R, 0.063W, 1.5A, -55DEGC/+155DEGC, 0402, SMD; Additional Datasheet URL: N/A; AutoDoc File: https://notefied-dynamic-precision.com/DB/Apps/Desktop/Item/Object.aspx?id=114568; BU Name: TEXAS INSTRUMENTS NORWAY; Budget Currency: EUR; Budget Price: 0.007; Budgetary Price: 0.007 EUR; CLASS: DISCRETE; Client Status: UNDER_REVIEW; Country of Origin: Israel; Datasheet URL: http://www.vishay.com/docs/20035/dcrcwe3.pdf; Datasheet URL 1: http://www.vishay.com/docs/20035/dcrcwe3.pdf; Datasheet URL 2: N/A; Definied Quality: INDUSTRIAL; Esd Level: N/A; Exclusive for Customers: TEXAS INSTRUMENTS NORWAY; Lead Time: 14; LifeCycle Status: ACTIVE; MPN: RK73Z1ETTP; MPN Status: ACTIVE; MSL: 1; MTBF: N/A; MTBF Standard: N/A; Manufacturer: KOA SPEER; Mass: 0.0006152g; Max Oper Temp: +155DEGC; Max TC: N/A; Max Tol: N/A; Maximum Operating Temperature: +155DEGC; Maximum Temperature Coefficient: N/A; Maximum Tolerance: +0.02R; Min Oper Temp: -55DEGC; Min TC: N/A; Min Tol: N/A; Minimum Operating Temperature: -55DEGC; Minimum Temperature Coeficient: N/A; Minimum Tolerance: 0R; Mounting Type: SMD; NOTE Status: PREFERRED; NOTEfied URL: https://notefied-dynamic-precision.com/NOTEfiedWebInterface/part/show?partNumber=01-22495; Notes: Standard item: Duplicate Reason: custom footprint for TEXAS INSTRUMENTS NORWAY.; Old Footprint: RESC1005X40N,0402; PCB Package: 0402; Packing Size: 10000; Packing Type: Tape & Reel; Part Number: 01-22495; Part Type: Resistor|0402|JUMPER; REACH/SVHC Compliance: Compliant; REACH/SVHC Details: SVHC List Version Jul 07, 2017; REACH/SVHC Source: REACH Declaration; REACH/SVHC Status: Unaffected; REACH/SVHC_COMPLIANCE: COMPLIANT; REACH/SVHC_DETAILS: SVHC LIST VERSION Jun 20, 2016; REACH/SVHC_SOURCE: MATERIAL DECLARATION; REACH/SVHC_STATUS: UNAFFECTED; ROHS: Exempt; Rated Current: 1.5A; Rated Power: 0.063W; Rated Voltage: N/A; Resistor Type: THICK FILM; Revision: R021; RoHS Status: ROHS_COMPLIANT_WITH_EXEMPTION; Rtd Current: N/A; Rtd Power: 0.063W; Rtd Voltage: 50V; Status: Released; Texas Part Status: Under Review; Type: Resistor; Vendor: VISHAY; Vendor Part Number: CRCW04020000Z0ED; Vendor Part Status: Active; WEIGHT: 0.0006152g
U1 = IC_RF_CC2652RB1FRGZ_QFN48: IC, CUSTOM, CC2652RB1FRGZ, QFN48-EP, SMD; ALT_SYMBOLS: QFNFC50P700X700X100-49A2L,QFNFC50P700X700X100-49A2M; Additional Datasheet URL: N/A; Datasheet URL: www.ti.com; Exclusive for Customers: TEXAS INSTRUMENTS NORWAY; Mass: N/A; Maximum Operating Temperature: N/A; Minimum Operating Temperature: N/A; Mounting Type: SMD; NOTEfied URL: https://notefied-dynamic-precision.com/NOTEfiedWebInterface/part/show?partNumber=18-35094; Notes: Custom item: Custom component.; PCB Package: QFN48-EP; Packing Size: N/A; Packing Type: Missing Info; Part Number: 18-35094; Part Type: IC|CUSTOM; REACH/SVHC Compliance: Missing Info; REACH/SVHC Details: N/A; REACH/SVHC Source: N/A; REACH/SVHC Status: Missing Info; ROHS: Missing Info; Rated Voltage: N/A; Revision: R007; Status: Released; Texas Part Status: Under Review; Type: IC; Vendor: TEXAS INSTRUMENTS; Vendor Part Number: CC2652RB1FRGZ; Vendor Part Status: Active
Y1 = CRYSTAL: CRYSTAL, RESONATOR, 32.768kHz, -40DEGC/+85DEGC, SMD; ALT_SYMBOLS: XTAL_FC135_A2L,XTAL_FC135_A2M; Additional Datasheet URL: http://www5.epsondevice.com/en/products/crystal_unit/fc135.html; AutoDoc File: https://notefied-dynamic-precision.com/DB/Apps/Desktop/Item/Object.aspx?id=91966; BU Name: DYNAMIC PRECISION GDANSK; Budget Currency: EUR; Budget Price: 0.61; Budgetary Price: 0.405 USD; CLASS: IC; Capacitance: 7pF; Client Status: UNDER_REVIEW; Country of Origin: Japan; Datasheet URL: https://support.epson.biz/td/api/doc_check.php?dl=brief_FC-135&lang=en; Datasheet URL 1: https://support.epson.biz/td/api/doc_check.php?mode=dl&lang=en&Parts=FC-135; Datasheet URL 2: http://www5.epsondevice.com/en/products/khz_range/fc135.html; Definied Quality: INDUSTRIAL; Esd Level: N/A; Lead Time: 10; MPN: FC-135 32.7680KA-AG0; MPN Status: ACTIVE; MSL: N/A; MTBF: N/A; MTBF Standard: N/A; Manufacturer: EPSON; Mass: 0.016g; Max Oper Temp: +85DEGC; Max TC: N/A; Max Tol: +20PPM; Maximum Operating Temperature: +85DEGC; Maximum Stability: N/A; Maximum Tolerance: +20PPM; Min Oper Temp: -40DEGC; Min TC: N/A; Min Tol: -20PPM; Minimum Operating Temperature: -40DEGC; Minimum Stability: N/A; Minimum Tolerance: -20PPM; Mounting Type: SMD; NOTE Status: PREFERRED; NOTEfied URL: https://notefied-dynamic-precision.com/NOTEfiedWebInterface/part/show?partNumber=12-00546; Notes: This device contains Lead titanium trioxide, CAS No. 12060-00-3, which exceeds the 0.1% SVHC limit. / Alias p/n:Q13FC13500002; Old Footprint: XTAL_FC-135N; Packing Size: 1000; Packing Type: Tape & Reel; Part Number: 12-00546; Part Type: Crystal|RESONATOR; REACH/SVHC Compliance: Non-Compliant; REACH/SVHC Details: SVHC List Version Jan 15, 2019; REACH/SVHC Source: REACH Declaration; REACH/SVHC Status: Affected; REACH/SVHC_COMPLIANCE: COMPLIANT; REACH/SVHC_DETAILS: SVHC LIST VERSION Dec 17, 2015; REACH/SVHC_SOURCE: REACH DECLARATION; REACH/SVHC_STATUS: UNAFFECTED; ROHS: Exempt; Rated Voltage: N/A; Revision: R019; RoHS Status: ROHS_COMPLIANT_WITH_EXEMPTION; Rtd Voltage: N/A; Status: Released; Texas Part Status: Under Review; Type: Crystal; Vendor: EPSON; Vendor Part Number: FC-135 32.7680KA-AG0; Vendor Part Status: Active; WEIGHT: N/A
Y2 = XTAL_4PINS_1_3: CRYSTAL, RESONATOR, 48MHz, -85PPM/+85PPM, -40DEGC/+125DEGC, SMD; ALT_SYMBOLS: OSCCC200X160X50-4B2L,OSCCC200X160X50-4B2M; Additional Datasheet URL: http://www.ndk.com/en/products/search/crystal/1190853_1494.html; AutoDoc File: https://notefied-dynamic-precision.com/DB/Apps/Desktop/Item/Object.aspx?id=116070; BU Name: TEXAS INSTRUMENTS NORWAY; Capacitance: 7pF; Client Status: UNDER_REVIEW; Datasheet URL: http://www.ndk.com/images/products/catalog/c_NX2016SA-2_e.pdf; Datasheet URL 1: https://notefied-dynamic-precision.com/db/Apps/OpenDocument.aspx?obj=5&docid=247737; Datasheet URL 2: http://www.ndk.com/images/products/catalog/c_NX2016SA_e.pdf; Exclusive for Customers: TEXAS INSTRUMENTS NORWAY; Mass: N/A; Max Oper Temp: +125DEGC; Max TC: +85PPM; Max Tol: +10PPM; Maximum Operating Temperature: +125DEGC; Maximum Stability: +85PPM; Maximum Tolerance: +10PPM; Min Oper Temp: -40DEGC; Min TC: -85PPM; Min Tol: -10PPM; Minimum Operating Temperature: -40DEGC; Minimum Stability: -85PPM; Minimum Tolerance: -10PPM; Mounting Type: SMD; NOTEfied URL: https://notefied-dynamic-precision.com/NOTEfiedWebInterface/part/show?partNumber=12-01232; Notes: Custom item:Documentation specified for the client; Packing Size: 3000; Packing Type: Tape & Reel; Part Number: 12-01232; Part Type: Crystal|RESONATOR; REACH/SVHC Compliance: Compliant; REACH/SVHC Details: SVHC List Version Jun 20, 2016; REACH/SVHC Source: REACH Declaration; REACH/SVHC Status: Unaffected; ROHS: Compliant; Rated Voltage: N/A; Revision: R016; RoHS Status: ROHS_COMPLIANT; Rtd Voltage: N/A; Status: Released; Texas Part Status: Under Review; Type: Crystal; Vendor: NIHON DEMPA KOGYO; Vendor Part Number: NX2016SA 48.000MHz EXS00A-CS05517; Vendor Part Status: Active
FIDU1-FIDU6 = FIDMARK: NON COMPONENT, FIDUCIAL MARK, ROUND 1mm, SMD; Additional Datasheet URL: N/A; AutoDoc File: https://notefied-dynamic-precision.com/DB/Apps/Desktop/Item/Object.aspx?id=74548; BU Name: DYNAMIC PRECISION GDANSK; CLASS: IO; Country of Origin: Missing Info; Datasheet URL: N/A; Mass: N/A; Mounting Type: SMD; NOTEfied URL: https://notefied-dynamic-precision.com/NOTEfiedWebInterface/part/show?partNumber=19-00111; Old Footprint: FID100X115; Packing Size: N/A; Packing Type: Missing Info; Part Number: 19-00111; Part Type: Non Component|FIDUCIAL; ROHS: Compliant; Revision: R015; Status: Released; Type: Non Component; Vendor: NON_COMPONENT; Vendor Part Number: FIDUCIAL_1mm; Vendor Part Status: Active

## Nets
GND: A1.2(GND) A1.3(GND) C3.2 C4.2 C5.2 C6.2 C7.2 C8.2 C9.2 C13.1 C15.2 C16.2 C17.2 C18.2 C19.2 C20.2 C21.1 C31.2 J1.2 J1.3 J1.4 J1.5 P1.1 P1.19 P2.2 P2.20 U1.49(VSS) Y2.2(GND) Y2.4(GND)
VDD_EB: FL1.2 P2.7 P2.9
VDDR: C8.1 C9.1 C16.1 L1.2 U1.45(VDDR) U1.48(VDDR)
VDDS: C3.1 C4.1 C5.1 C6.1 C7.1 FL1.1 R1.2 U1.13(VDDS2) U1.22(VDDS3) U1.34(VDDS_DCDC) U1.44(VDDS)
DCDC_SW: L1.1 U1.33(DCDC_SW)
DIO_0: P1.3 U1.5(DIO_0)
DIO_1: P1.5 U1.6(DIO_1)
DIO_2: P1.7 U1.7(DIO_2)
DIO_3: P1.9 U1.8(DIO_3)
DIO_4: P1.11 U1.9(DIO_4)
DIO_5: P1.13 U1.10(DIO_5)
DIO_6: P1.4 U1.11(DIO_6)
DIO_7: P1.2 U1.12(DIO_7)
DIO_8: P1.20 U1.14(DIO_8)
DIO_9: P1.18 U1.15(DIO_9)
DIO_10: P1.16 U1.16(DIO_10)
DIO_11: P1.14 U1.17(DIO_11)
DIO_12: P1.12 U1.18(DIO_12)
DIO_13: P1.15 U1.19(DIO_13)
DIO_14: P1.17 U1.20(DIO_14)
DIO_15: P1.6 U1.21(DIO_15)
DIO_16 / JTAG TDO: P2.19 U1.26(DIO_16)
DIO_17 / JTAG TDI: P2.17 U1.27(DIO_17)
DIO_18: P1.8 U1.28(DIO_18)
DIO_19: P1.10 U1.29(DIO_19)
DIO_20: P2.8 U1.30(DIO_20)
DIO_21: P2.18 U1.31(DIO_21)
DIO_22: DIO22.1 U1.32(DIO_22)
DIO_23: P2.5 U1.36(DIO_23)
DIO_24: P2.10 U1.37(DIO_24)
DIO_25: P2.11 U1.38(DIO_25)
DIO_26: P2.6 U1.39(DIO_26)
DIO_27: P2.13 U1.40(DIO_27)
DIO_28: P2.16 U1.41(DIO_28)
DIO_29: P2.14 U1.42(DIO_29)
DIO_30: P2.12 U1.43(DIO_30)
JTAG_TCK: P2.1 U1.25(JTAG_TCKC)
JTAG_TMS: P2.4 U1.24(JTAG_TMSC)
nRESET: C20.1 P2.15 R1.1 U1.35(RESET_N)
N310466: U1.47(X48M_P) Y2.1
N310868: U1.46(X48M_N) Y2.3
N314427: C21.2 L21.1 U1.2(RF_N)
N314470: C11.1 L11.1 U1.1(RF_P)
N314514: C31.1 L11.2
N314764: C11.2 L12.1 L21.2
N315193: C13.2 L12.2 L13.1
N316022: A1.1(FEED) C15.1 R12.1
N316040: C24.1 J1.1
N316649: C19.1 U1.23(DCOUPL)
N316919: C17.1 U1.3(X32K_Q1) Y1.1
N316932: C18.1 U1.4(X32K_Q2) Y1.2
N334495: C14.1 C24.2 L13.2
N356130: C14.2 R12.2

Not connected (* = marked no-connect by the designer): FIDU1 1*; FIDU2 1*; FIDU3 1*; FIDU4 1*; FIDU5 1*; FIDU6 1*; P2 3*

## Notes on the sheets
sheet 2
- Revision history:
  A0
  ---------------------------------------------------------------------------------------------
  - Based on CC26x2EM-7ID Rev B0
  - Set Y2, 48 MHz crystal as do not mount (DNM)
  - Set Y1, 32 kHz crystal as do not mount (DNM)
  - Set C17, as do not mount (DNM)
  - Set C18, as do not mount (DNM)
  - Change C19 from 1uF (GRM155R61C105KA12D) to 10 uF (GRM155R60J106ME15D)
  - Updated U1 from CC26x2R1FRGZ (Notified 18-34913) to CC2652RB1FRG (Notified 18-35094)
  B0
  ---------------------------------------------------------------------------------------------
  - Removing TI logo from silk skreen
  - Removing PB free logo
sheet 3
- VDDS Decoupling Capacitors
- VDDR Decoupling Capacitors
- Pin 13
- Pin 22
- Pin 44
- Pin 34
- Pin 45
- Pin 48
- Place L1 and
  C8 close to pin 33
- Mount either
  C24 or C14
  To select SMA
  or PCB ant.
  Note that a
  DC-blocking
  capacitor must
  be used if
  antenna
  has DC-path
  to ground.
- R12 and C15 for
  antenna matching
- EM connector 1
- EM connector 2
